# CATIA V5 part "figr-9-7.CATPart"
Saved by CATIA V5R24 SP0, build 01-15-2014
Part number: Part2
Bounding box of the stored display mesh (mm): x -96.278 to 96.278, y -96.278 to 96.278, z -26.878 to 0
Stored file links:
  D:\KAVITA\CATIA V5-6R2014 Project_ Kavita\CATIA V5-6R2014_partfiles\Partfiles\c09_catia_v5-6r2014_prt\figr-9-7.CATPart
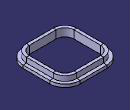
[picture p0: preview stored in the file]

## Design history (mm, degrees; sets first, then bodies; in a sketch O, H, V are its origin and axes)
Body1 (main body)
  Sketch1 on xy-plane, origin (0, 0, 0), H (1, 0, 0), V (0, 1, 0)
    point P1 (-75, 75)
    line L1 (-45, 75) -> (45, 75)
    line L2 (75, 45) -> (75, -45)
    line L3 (45, -75) -> (-45, -75)
    line L4 (-75, -45) -> (-75, 45)
    point P2 (75, 75)
    point P3 (75, -75)
    point P4 (-75, -75)
    axis line L5 (75, -75) -> (-75, 75)
    arc A1 centre (45, -45) radius 30 from (75, -45) to (45, -75) cw
    arc A2 centre (45, 45) radius 30 from (45, 75) to (75, 45) cw
    arc A3 centre (-45, 45) radius 30 from (-45, 75) to (-75, 45) ccw
    arc A4 centre (-45, -45) radius 30 from (-45, -75) to (-75, -45) cw
    distance P2 P3 = 150
    distance P3 P4 = 150
    radius A1 = 30
    radius A2 = 30
    radius A3 = 30
    radius A4 = 30
    horizontal: L1 H, L3 H
    vertical: L2 V, L4 V
    midpoint: O L5
    coincidence: L2 P3, L3 P3, L1 P2, L2 P2, L1 P1, L4 P1, L3 P4, L4 P4
    tangency: A1 L2, A1 L3, A2 L1, A2 L2, A3 L1, A3 L4, A4 L3, A4 L4
  Sketch2 on yz-plane, origin (0, 0, 0), H (0, 1, 0), V (0, 0, 1)
    point P1 (85, 0)
    line L1 (85, 0) -> (85, -16.8782)
    line L2 (85, -16.8782) -> (96.2781, -16.8782)
    line L3 (96.2781, -16.8782) -> (96.2781, -26.8782)
    line L4 (96.2781, -26.8782) -> (75, -26.8782)
    line L5 (75, -26.8782) -> (75, 0)
    point P6 (75, 0)
    line L6 (75, 0) -> (85, 0)
    reference projected point E1 (75, 0) from edge of Sketch1
    length L3 = 10
    length L6 = 10
    coincidence: P1 H, P6 H, P6 E1
    vertical: L1 V, L3 V, L5 V
    horizontal: L2 H, L4 H, L6 H
  Rib1: profile Sketch2, centre curve Sketch1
